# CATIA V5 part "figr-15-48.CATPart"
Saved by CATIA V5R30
Part number: Part1
Bounding box of the stored display mesh (mm): x 0 to 69.121, y -21.475 to 20.775, z 0 to 47.185
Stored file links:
  D:\PROJECTS\CATIA V56R 2020\Resources\Parts File\c15_catia_v5_6r2020_prt\figr-15-48.CATPart
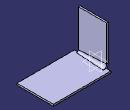
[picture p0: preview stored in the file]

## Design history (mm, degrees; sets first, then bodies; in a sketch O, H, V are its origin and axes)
SheetMetalParameters1: Thickness 2, BendRadius 4, KFactor 0.400515 {= log(min(100,max(20*SheetMetalParameters1.BendRadius,SheetMetalParameters1.Thickness)/SheetMetalParameters1.Thickness))/log(100)/2}, ReliefRadialLength 1, ReliefAxialLength 2, MinimumBendRadius 0
Body1 (main body)
  Sketch1 on xy-plane, origin (0, 0, 0), H (1, 0, 0), V (0, 1, 0)
    line L1 (2.4998, 20.7748) -> (69.1212, 20.7748)
    line L2 (69.1212, 20.7748) -> (69.1212, -21.4753)
    line L3 (69.1212, -21.4753) -> (2.4998, -21.4753)
    line L4 (2.4998, -21.4753) -> (2.4998, 20.7748)
    horizontal: L1 H, L3 H
    vertical: L2 V, L4 V
  Wall1: Thickness 2, Profile Sketch1
  Sketch2 on yz-plane, origin (0, 0, 0), H (0, 1, 0), V (0, 0, 1)
    line L1 (-17.3994, 47.1851) -> (15.4124, 47.1851)
    line L2 (15.4124, 47.1851) -> (15.4124, 3.5135)
    line L3 (15.4124, 3.5135) -> (-17.3994, 3.5135)
    line L4 (-17.3994, 3.5135) -> (-17.3994, 47.1851)
    horizontal: L1 H, L3 H
    vertical: L2 V, L4 V
  Wall2: Thickness 2, Profile Sketch2
  d_Bend1: Bend_Thickness 2, Bend_KFactor 0.36928 {= log(min(100,max(20*d_Bend1.Bend_KFactorRadius,SheetMetalParameters1.Thickness)/SheetMetalParameters1.Thickness))/log(100)/2}, Bend_FirstSupport Wall1, Bend_SecondSupport Wall2, Bend_KFactorRadius 3 {= ( d_Bend1.ConicalBendSurf_FirstRadius + d_Bend1.ConicalBendSurf_SecondRadius ) / 2.0}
